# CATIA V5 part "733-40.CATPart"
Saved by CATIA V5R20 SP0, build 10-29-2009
Part number: 733-40
Bounding box of the stored display mesh (mm): x -33 to 33, y -32.999 to 32.999, z -37 to 71
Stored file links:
  C:\Users\Utente\Desktop\IO LAVORO\3D X SITO CF\X SITO\733\733-40.CATPart
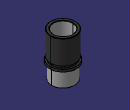
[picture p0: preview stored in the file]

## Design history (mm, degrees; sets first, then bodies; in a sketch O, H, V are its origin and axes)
Set1
  DatumSurface1 to DatumSurface25 "733-40"
Body1 (main body)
